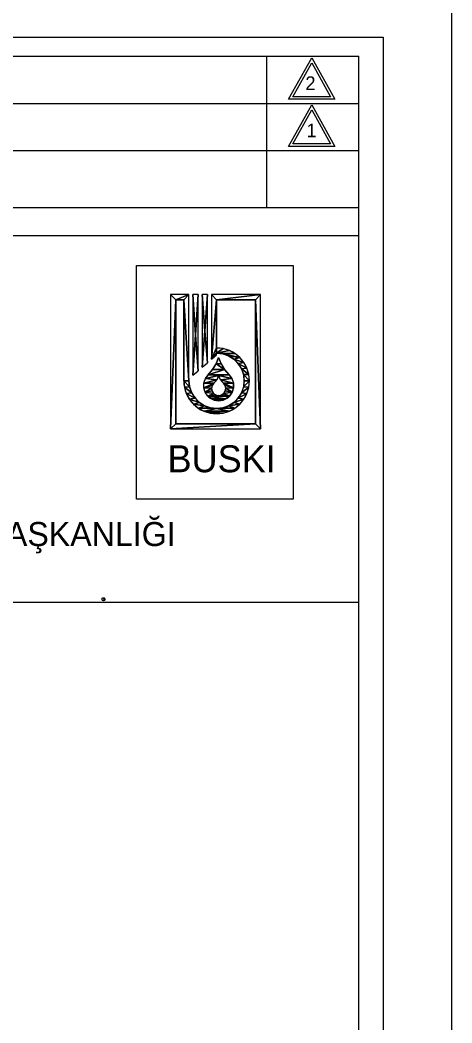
# Model space of a CAD drawing. Extents: x 314 to 1145, y -10 to 574.
# Drawn here: x 1082.1 to 1145, y 143.5 to 289.5 of the extents above; entities that cross this region are included whole.
import ezdxf

# ---------------------------------------------------------------- set-up
doc = ezdxf.new("R2010")
doc.units = 0
for name, color, linetype in [('Level 1', 7, 'Continuous'), ('Level 20', 7, 'Continuous'), ('Level 21', 7, 'Continuous'), ('Level 51', 7, 'Continuous'), ('Level 6', 7, 'Continuous'), ('Level 7', 7, 'Continuous'), ('Level 8', 7, 'Continuous')]:
    doc.layers.add(name, color=color, linetype=linetype)

msp = doc.modelspace()

# ---------------------------------------------------------------- linework, layer by layer
at = {"layer": 'Level 1'}
for p, q in [((960, 287), (1135, 287)), ((1135, 287), (1135, 0))]:
    msp.add_line(p, q, dxfattribs=at)
msp.add_lwpolyline([(1094.31, 205.37), (1094.35, 205.37), (1094.43, 205.33), (1094.48, 205.24), (1094.48, 205.07), (1094.39, 204.99), (1094.26, 204.94), (1094.14, 204.99), (1094.05, 205.07), (1094.05, 205.24), (1094.09, 205.33), (1094.18, 205.37), (1094.31, 205.37), (1094.43, 205.24), (1094.43, 205.11), (1094.35, 205.03), (1094.26, 204.94), (1094.35, 205.07), (1094.35, 205.28), (1094.31, 205.37)], dxfattribs=at)
msp.add_lwpolyline([(1094.31, 205.37), (1094.35, 205.37), (1094.43, 205.33), (1094.48, 205.24), (1094.48, 205.07), (1094.39, 204.99), (1094.26, 204.94), (1094.14, 204.99), (1094.05, 205.07), (1094.05, 205.24), (1094.09, 205.33), (1094.18, 205.37), (1094.31, 205.37), (1094.43, 205.24), (1094.43, 205.11), (1094.35, 205.03), (1094.26, 204.94), (1094.35, 205.07), (1094.35, 205.28), (1094.31, 205.37)], dxfattribs=at)
msp.add_lwpolyline([(1094.31, 205.37), (1094.35, 205.37), (1094.43, 205.33), (1094.48, 205.24), (1094.48, 205.07), (1094.39, 204.99), (1094.26, 204.94), (1094.14, 204.99), (1094.05, 205.07), (1094.05, 205.24), (1094.09, 205.33), (1094.18, 205.37), (1094.31, 205.37), (1094.43, 205.24), (1094.43, 205.11), (1094.35, 205.03), (1094.26, 204.94), (1094.35, 205.07), (1094.35, 205.28), (1094.31, 205.37)], dxfattribs=at)
msp.add_lwpolyline([(1094.31, 205.37), (1094.35, 205.37), (1094.43, 205.33), (1094.48, 205.24), (1094.48, 205.07), (1094.39, 204.99), (1094.26, 204.94), (1094.14, 204.99), (1094.05, 205.07), (1094.05, 205.24), (1094.09, 205.33), (1094.18, 205.37), (1094.31, 205.37), (1094.43, 205.24), (1094.43, 205.11), (1094.35, 205.03), (1094.26, 204.94), (1094.35, 205.07), (1094.35, 205.28), (1094.31, 205.37)], dxfattribs=at)
at = {"layer": 'Level 51'}
msp.add_lwpolyline([(314, -10), (1145, -10), (1145, 574), (314, 574)], close=True, dxfattribs=at)
at = {"layer": 'Level 6'}
for p, q in [((963.47, 284.22), (1131.45, 284.22)), ((963.47, 284.22), (1131.45, 284.22)), ((963.47, 284.22), (1131.45, 284.22)), ((963.47, 284.22), (1131.45, 284.22)), ((966.6, 284.22), (1128.32, 284.22)), ((966.6, 284.22), (1128.32, 284.22)), ((966.6, 284.22), (1128.32, 284.22)), ((966.6, 284.22), (1128.32, 284.22)), ((966.6, 284.22), (1128.32, 284.22)), ((966.6, 284.22), (1128.32, 284.22)), ((966.6, 284.22), (1128.32, 284.22)), ((966.6, 284.22), (1128.32, 284.22)), ((1118.07, 262.2), (1118.07, 284.22)), ((1118.07, 262.2), (1118.07, 284.22)), ((1118.07, 262.2), (1118.07, 284.22)), ((1118.07, 262.2), (1118.07, 284.22)), ((1131.45, 260.69), (1131.45, 284.22)), ((1131.45, 260.69), (1131.45, 284.22)), ((1131.45, 260.69), (1131.45, 284.22)), ((1131.45, 260.69), (1131.45, 284.22)), ((1131.45, 260.69), (1131.45, 284.22)), ((1131.45, 260.69), (1131.45, 284.22)), ((1131.45, 260.69), (1131.45, 284.22)), ((1131.45, 260.69), (1131.45, 284.22)), ((963.47, 277.35), (1131.45, 277.35)), ((963.47, 277.35), (1131.45, 277.35)), ((963.47, 277.35), (1131.45, 277.35)), ((963.47, 277.35), (1131.45, 277.35)), ((963.47, 270.49), (1131.45, 270.49)), ((963.47, 270.49), (1131.45, 270.49)), ((963.47, 270.49), (1131.45, 270.49)), ((963.47, 270.49), (1131.45, 270.49)), ((1131.45, 4.97), (1131.45, 267.9)), ((1131.45, 4.97), (1131.45, 267.9)), ((1131.45, 4.97), (1131.45, 267.9)), ((1131.45, 4.97), (1131.45, 267.9)), ((963.47, 262.2), (1131.45, 262.2)), ((963.47, 262.2), (1131.45, 262.2)), ((963.47, 262.2), (1131.45, 262.2)), ((963.47, 262.2), (1131.45, 262.2)), ((963.47, 258.11), (1131.45, 258.11)), ((963.47, 258.11), (1131.45, 258.11)), ((963.47, 258.11), (1131.45, 258.11)), ((963.47, 258.11), (1131.45, 258.11)), ((963.47, 204.75), (1131.45, 204.75)), ((963.47, 204.75), (1131.45, 204.75)), ((963.47, 204.75), (1131.45, 204.75)), ((963.47, 204.75), (1131.45, 204.75))]:
    msp.add_line(p, q, dxfattribs=at)
at = {"layer": 'Level 7'}
for points in [[(1121.21, 277.97), (1124.58, 284.02), (1127.95, 277.97)], [(1121.21, 277.97), (1124.58, 284.02), (1127.95, 277.97)], [(1121.21, 277.97), (1124.58, 284.02), (1127.95, 277.97)], [(1121.21, 277.97), (1124.58, 284.02), (1127.95, 277.97)], [(1121.83, 278.34), (1124.58, 283.27), (1127.33, 278.34)], [(1121.83, 278.34), (1124.58, 283.27), (1127.33, 278.34)], [(1121.83, 278.34), (1124.58, 283.27), (1127.33, 278.34)], [(1121.83, 278.34), (1124.58, 283.27), (1127.33, 278.34)], [(1121.21, 271.11), (1124.58, 277.16), (1127.95, 271.11)], [(1121.21, 271.11), (1124.58, 277.16), (1127.95, 271.11)], [(1121.21, 271.11), (1124.58, 277.16), (1127.95, 271.11)], [(1121.21, 271.11), (1124.58, 277.16), (1127.95, 271.11)], [(1121.83, 271.48), (1124.58, 276.41), (1127.33, 271.48)], [(1121.83, 271.48), (1124.58, 276.41), (1127.33, 271.48)], [(1121.83, 271.48), (1124.58, 276.41), (1127.33, 271.48)], [(1121.83, 271.48), (1124.58, 276.41), (1127.33, 271.48)]]:
    msp.add_lwpolyline(points, close=True, dxfattribs=at)
at = {"layer": 'Level 8'}
for points in [[(1099.09, 253.77), (1121.88, 253.77), (1121.88, 219.76), (1099.09, 219.76)], [(1104.03, 249.52), (1104.03, 229.97), (1104.79, 248.76)], [(1104.79, 248.76), (1106.71, 249.52), (1104.03, 249.52)], [(1104.03, 249.52), (1104.03, 229.97), (1104.79, 248.76)], [(1104.79, 248.76), (1106.71, 249.52), (1104.03, 249.52)], [(1104.79, 248.76), (1104.03, 229.97), (1104.79, 230.73)], [(1104.79, 248.76), (1104.03, 229.97), (1104.79, 230.73)], [(1106.71, 249.52), (1104.79, 248.76), (1105.95, 248.76)], [(1106.71, 249.52), (1104.79, 248.76), (1105.95, 248.76)], [(1106.71, 249.52), (1105.95, 248.76), (1106.71, 236.97)], [(1106.71, 249.52), (1105.95, 248.76), (1106.71, 236.97)], [(1105.95, 248.76), (1105.95, 236.97), (1106.71, 236.97)], [(1105.95, 248.76), (1105.95, 236.97), (1106.71, 236.97)], [(1107.67, 243.65), (1108.05, 249.52), (1107.29, 249.52)], [(1107.67, 243.65), (1107.29, 249.52), (1107.29, 237.79)], [(1107.67, 243.65), (1108.05, 249.52), (1107.29, 249.52)], [(1107.67, 243.65), (1107.29, 249.52), (1107.29, 237.79)], [(1107.67, 243.65), (1108.05, 238.43), (1108.05, 249.52)], [(1107.67, 243.65), (1108.05, 238.43), (1108.05, 249.52)], [(1109.02, 244.24), (1109.4, 249.52), (1108.64, 249.52)], [(1109.02, 244.24), (1108.64, 249.52), (1108.64, 238.96)], [(1109.02, 244.24), (1109.4, 249.52), (1108.64, 249.52)], [(1109.02, 244.24), (1108.64, 249.52), (1108.64, 238.96)], [(1109.02, 244.24), (1109.4, 239.6), (1109.4, 249.52)], [(1109.02, 244.24), (1109.4, 239.6), (1109.4, 249.52)], [(1109.98, 249.52), (1109.98, 240.12), (1110.74, 248.76)], [(1110.74, 248.76), (1117.15, 249.52), (1109.98, 249.52)], [(1109.98, 249.52), (1109.98, 240.12), (1110.74, 248.76)], [(1110.74, 248.76), (1117.15, 249.52), (1109.98, 249.52)], [(1110.74, 248.76), (1109.98, 240.12), (1110.74, 241.76)], [(1110.74, 248.76), (1109.98, 240.12), (1110.74, 241.76)], [(1117.15, 249.52), (1110.74, 248.76), (1116.4, 248.76)], [(1117.15, 249.52), (1110.74, 248.76), (1116.4, 248.76)], [(1117.15, 249.52), (1116.4, 248.76), (1117.15, 229.97)], [(1117.15, 249.52), (1116.4, 248.76), (1117.15, 229.97)], [(1116.4, 248.76), (1116.4, 230.73), (1117.15, 229.97)], [(1116.4, 248.76), (1116.4, 230.73), (1117.15, 229.97)], [(1109.02, 244.24), (1108.64, 238.96), (1109.4, 239.6)], [(1109.02, 244.24), (1108.64, 238.96), (1109.4, 239.6)], [(1107.67, 243.65), (1107.29, 237.79), (1108.05, 238.43)], [(1107.67, 243.65), (1107.29, 237.79), (1108.05, 238.43)], [(1110.74, 241.76), (1109.98, 240.12), (1110.74, 241)], [(1110.74, 241.76), (1109.98, 240.12), (1110.74, 241)], [(1110.74, 241), (1109.98, 240.12), (1110.74, 240.77)], [(1110.74, 241), (1109.98, 240.12), (1110.74, 240.77)], [(1110.74, 241.76), (1110.74, 241), (1111.67, 241.66)], [(1110.74, 241.76), (1110.74, 241), (1111.67, 241.66)], [(1111.67, 241.66), (1110.74, 241), (1112.57, 241.39)], [(1111.67, 241.66), (1110.74, 241), (1112.57, 241.39)], [(1112.57, 241.39), (1110.74, 241), (1113.39, 240.95)], [(1112.57, 241.39), (1110.74, 241), (1113.39, 240.95)], [(1110.74, 241), (1111.63, 240.9), (1113.39, 240.95)], [(1110.74, 241), (1111.63, 240.9), (1113.39, 240.95)], [(1113.39, 240.95), (1111.63, 240.9), (1114.12, 240.36)], [(1113.39, 240.95), (1111.63, 240.9), (1114.12, 240.36)], [(1111.03, 240.36), (1111.39, 239.44), (1110.67, 239.44)], [(1111.03, 240.36), (1111.39, 239.44), (1110.67, 239.44)], [(1111.63, 240.9), (1112.48, 240.6), (1114.12, 240.36)], [(1111.63, 240.9), (1112.48, 240.6), (1114.12, 240.36)], [(1112.48, 240.6), (1113.25, 240.12), (1114.12, 240.36)], [(1112.48, 240.6), (1113.25, 240.12), (1114.12, 240.36)], [(1114.12, 240.36), (1113.25, 240.12), (1114.71, 239.63)], [(1114.12, 240.36), (1113.25, 240.12), (1114.71, 239.63)], [(1113.25, 240.12), (1113.88, 239.48), (1114.71, 239.63)], [(1113.25, 240.12), (1113.88, 239.48), (1114.71, 239.63)], [(1114.71, 239.63), (1113.88, 239.48), (1115.16, 238.8)], [(1114.71, 239.63), (1113.88, 239.48), (1115.16, 238.8)], [(1113.88, 239.48), (1114.36, 238.72), (1115.16, 238.8)], [(1113.88, 239.48), (1114.36, 238.72), (1115.16, 238.8)], [(1111.9, 238.6), (1112.55, 237.85), (1109.51, 237.85)], [(1110.16, 238.6), (1111.9, 238.6), (1109.51, 237.85)], [(1111.9, 238.6), (1112.55, 237.85), (1109.51, 237.85)], [(1110.16, 238.6), (1111.9, 238.6), (1109.51, 237.85)], [(1110.67, 239.44), (1111.9, 238.6), (1110.16, 238.6)], [(1110.67, 239.44), (1111.9, 238.6), (1110.16, 238.6)], [(1111.39, 239.44), (1111.9, 238.6), (1110.67, 239.44)], [(1111.39, 239.44), (1111.9, 238.6), (1110.67, 239.44)], [(1115.16, 238.8), (1114.36, 238.72), (1115.43, 237.91)], [(1115.16, 238.8), (1114.36, 238.72), (1115.43, 237.91)], [(1114.36, 238.72), (1114.66, 237.87), (1115.43, 237.91)], [(1114.36, 238.72), (1114.66, 237.87), (1115.43, 237.91)], [(1105.95, 236.97), (1106.04, 236.04), (1106.81, 236.08)], [(1106.71, 236.97), (1105.95, 236.97), (1106.81, 236.08)], [(1105.95, 236.97), (1106.04, 236.04), (1106.81, 236.08)], [(1106.71, 236.97), (1105.95, 236.97), (1106.81, 236.08)], [(1108.87, 236.64), (1110.33, 236.62), (1108.86, 235.95)], [(1108.87, 236.64), (1110.33, 236.62), (1108.86, 235.95)], [(1110.33, 236.62), (1110.09, 236.29), (1108.86, 235.95)], [(1110.33, 236.62), (1110.09, 236.29), (1108.86, 235.95)], [(1109.1, 237.3), (1110.76, 237.13), (1108.87, 236.64)], [(1109.1, 237.3), (1110.76, 237.13), (1108.87, 236.64)], [(1110.76, 237.13), (1110.33, 236.62), (1108.87, 236.64)], [(1110.76, 237.13), (1110.33, 236.62), (1108.87, 236.64)], [(1109.51, 237.85), (1111.03, 237.73), (1109.1, 237.3)], [(1109.51, 237.85), (1111.03, 237.73), (1109.1, 237.3)], [(1111.03, 237.73), (1110.76, 237.13), (1109.1, 237.3)], [(1111.03, 237.73), (1110.76, 237.13), (1109.1, 237.3)], [(1112.55, 237.85), (1111.03, 237.73), (1109.51, 237.85)], [(1112.55, 237.85), (1111.03, 237.73), (1109.51, 237.85)], [(1112.55, 237.85), (1112.96, 237.3), (1111.03, 237.73)], [(1112.55, 237.85), (1112.96, 237.3), (1111.03, 237.73)], [(1111.03, 237.73), (1112.96, 237.3), (1111.3, 237.13)], [(1111.03, 237.73), (1112.96, 237.3), (1111.3, 237.13)], [(1112.96, 237.3), (1113.18, 236.64), (1111.3, 237.13)], [(1112.96, 237.3), (1113.18, 236.64), (1111.3, 237.13)], [(1111.3, 237.13), (1113.18, 236.64), (1111.73, 236.62)], [(1111.3, 237.13), (1113.18, 236.64), (1111.73, 236.62)], [(1113.18, 236.64), (1113.19, 235.95), (1111.73, 236.62)], [(1113.18, 236.64), (1113.19, 235.95), (1111.73, 236.62)], [(1111.73, 236.62), (1113.19, 235.95), (1111.97, 236.29)], [(1111.73, 236.62), (1113.19, 235.95), (1111.97, 236.29)], [(1115.43, 237.91), (1114.66, 237.87), (1115.52, 236.97)], [(1115.43, 237.91), (1114.66, 237.87), (1115.52, 236.97)], [(1114.66, 237.87), (1114.76, 236.97), (1115.52, 236.97)], [(1114.66, 237.87), (1114.76, 236.97), (1115.52, 236.97)], [(1115.52, 236.97), (1114.66, 236.08), (1115.43, 236.04)], [(1114.76, 236.97), (1114.66, 236.08), (1115.52, 236.97)], [(1115.52, 236.97), (1114.66, 236.08), (1115.43, 236.04)], [(1114.76, 236.97), (1114.66, 236.08), (1115.52, 236.97)], [(1106.81, 236.08), (1106.04, 236.04), (1107.11, 235.23)], [(1106.81, 236.08), (1106.04, 236.04), (1107.11, 235.23)], [(1106.04, 236.04), (1106.32, 235.14), (1107.11, 235.23)], [(1106.04, 236.04), (1106.32, 235.14), (1107.11, 235.23)], [(1107.11, 235.23), (1106.32, 235.14), (1107.59, 234.46)], [(1107.11, 235.23), (1106.32, 235.14), (1107.59, 234.46)], [(1106.32, 235.14), (1106.76, 234.32), (1107.59, 234.46)], [(1106.32, 235.14), (1106.76, 234.32), (1107.59, 234.46)], [(1110.09, 236.29), (1110, 235.89), (1108.86, 235.95)], [(1110.09, 236.29), (1110, 235.89), (1108.86, 235.95)], [(1108.86, 235.95), (1110, 235.89), (1109.07, 235.3)], [(1108.86, 235.95), (1110, 235.89), (1109.07, 235.3)], [(1110, 235.89), (1110.07, 235.49), (1109.07, 235.3)], [(1110, 235.89), (1110.07, 235.49), (1109.07, 235.3)], [(1110.07, 235.49), (1110.29, 235.14), (1109.07, 235.3)], [(1110.07, 235.49), (1110.29, 235.14), (1109.07, 235.3)], [(1109.07, 235.3), (1110.29, 235.14), (1109.47, 234.74)], [(1109.07, 235.3), (1110.29, 235.14), (1109.47, 234.74)], [(1110.29, 235.14), (1110.63, 234.91), (1109.47, 234.74)], [(1110.29, 235.14), (1110.63, 234.91), (1109.47, 234.74)], [(1111.77, 235.14), (1112.59, 234.74), (1111.43, 234.91)], [(1111.77, 235.14), (1112.59, 234.74), (1111.43, 234.91)], [(1111.99, 235.49), (1112.99, 235.3), (1111.77, 235.14)], [(1111.99, 235.49), (1112.99, 235.3), (1111.77, 235.14)], [(1112.99, 235.3), (1112.59, 234.74), (1111.77, 235.14)], [(1112.99, 235.3), (1112.59, 234.74), (1111.77, 235.14)], [(1111.97, 236.29), (1113.19, 235.95), (1112.06, 235.89)], [(1111.97, 236.29), (1113.19, 235.95), (1112.06, 235.89)], [(1112.06, 235.89), (1112.99, 235.3), (1111.99, 235.49)], [(1112.06, 235.89), (1112.99, 235.3), (1111.99, 235.49)], [(1113.19, 235.95), (1112.99, 235.3), (1112.06, 235.89)], [(1113.19, 235.95), (1112.99, 235.3), (1112.06, 235.89)], [(1114.36, 235.23), (1113.88, 234.46), (1115.16, 235.14)], [(1114.36, 235.23), (1113.88, 234.46), (1115.16, 235.14)], [(1115.16, 235.14), (1113.88, 234.46), (1114.71, 234.32)], [(1115.16, 235.14), (1113.88, 234.46), (1114.71, 234.32)], [(1114.66, 236.08), (1114.36, 235.23), (1115.43, 236.04)], [(1114.66, 236.08), (1114.36, 235.23), (1115.43, 236.04)], [(1115.43, 236.04), (1114.36, 235.23), (1115.16, 235.14)], [(1115.43, 236.04), (1114.36, 235.23), (1115.16, 235.14)], [(1107.59, 234.46), (1106.76, 234.32), (1108.23, 233.83)], [(1107.59, 234.46), (1106.76, 234.32), (1108.23, 233.83)], [(1106.76, 234.32), (1107.36, 233.59), (1108.23, 233.83)], [(1106.76, 234.32), (1107.36, 233.59), (1108.23, 233.83)], [(1108.23, 233.83), (1107.36, 233.59), (1108.99, 233.35)], [(1108.23, 233.83), (1107.36, 233.59), (1108.99, 233.35)], [(1110.63, 234.91), (1111.03, 234.83), (1109.47, 234.74)], [(1110.63, 234.91), (1111.03, 234.83), (1109.47, 234.74)], [(1111.03, 234.83), (1112.59, 234.74), (1109.47, 234.74)], [(1111.03, 234.83), (1112.59, 234.74), (1109.47, 234.74)], [(1109.47, 234.74), (1112.03, 234.33), (1110.03, 234.33)], [(1112.59, 234.74), (1112.03, 234.33), (1109.47, 234.74)], [(1109.47, 234.74), (1112.03, 234.33), (1110.03, 234.33)], [(1112.59, 234.74), (1112.03, 234.33), (1109.47, 234.74)], [(1110.03, 234.33), (1111.37, 234.11), (1110.68, 234.11)], [(1112.03, 234.33), (1111.37, 234.11), (1110.03, 234.33)], [(1110.03, 234.33), (1111.37, 234.11), (1110.68, 234.11)], [(1112.03, 234.33), (1111.37, 234.11), (1110.03, 234.33)], [(1111.43, 234.91), (1112.59, 234.74), (1111.03, 234.83)], [(1111.43, 234.91), (1112.59, 234.74), (1111.03, 234.83)], [(1113.25, 233.83), (1112.48, 233.35), (1114.12, 233.59)], [(1113.25, 233.83), (1112.48, 233.35), (1114.12, 233.59)], [(1113.88, 234.46), (1113.25, 233.83), (1114.71, 234.32)], [(1113.88, 234.46), (1113.25, 233.83), (1114.71, 234.32)], [(1114.71, 234.32), (1113.25, 233.83), (1114.12, 233.59)], [(1114.71, 234.32), (1113.25, 233.83), (1114.12, 233.59)], [(1107.36, 233.59), (1108.08, 232.99), (1108.99, 233.35)], [(1107.36, 233.59), (1108.08, 232.99), (1108.99, 233.35)], [(1108.99, 233.35), (1108.08, 232.99), (1109.84, 233.05)], [(1108.99, 233.35), (1108.08, 232.99), (1109.84, 233.05)], [(1109.84, 233.05), (1108.08, 232.99), (1110.74, 232.95)], [(1109.84, 233.05), (1108.08, 232.99), (1110.74, 232.95)], [(1108.08, 232.99), (1108.91, 232.55), (1110.74, 232.95)], [(1108.08, 232.99), (1108.91, 232.55), (1110.74, 232.95)], [(1110.74, 232.95), (1108.91, 232.55), (1112.57, 232.55)], [(1110.74, 232.95), (1108.91, 232.55), (1112.57, 232.55)], [(1108.91, 232.55), (1109.8, 232.28), (1111.67, 232.28)], [(1112.57, 232.55), (1108.91, 232.55), (1111.67, 232.28)], [(1108.91, 232.55), (1109.8, 232.28), (1111.67, 232.28)], [(1112.57, 232.55), (1108.91, 232.55), (1111.67, 232.28)], [(1111.67, 232.28), (1109.8, 232.28), (1110.74, 232.19)], [(1111.67, 232.28), (1109.8, 232.28), (1110.74, 232.19)], [(1111.63, 233.05), (1110.74, 232.95), (1113.39, 232.99)], [(1111.63, 233.05), (1110.74, 232.95), (1113.39, 232.99)], [(1113.39, 232.99), (1110.74, 232.95), (1112.57, 232.55)], [(1113.39, 232.99), (1110.74, 232.95), (1112.57, 232.55)], [(1112.48, 233.35), (1111.63, 233.05), (1113.39, 232.99)], [(1112.48, 233.35), (1111.63, 233.05), (1113.39, 232.99)], [(1114.12, 233.59), (1112.48, 233.35), (1113.39, 232.99)], [(1114.12, 233.59), (1112.48, 233.35), (1113.39, 232.99)], [(1116.4, 230.73), (1104.03, 229.97), (1117.15, 229.97)], [(1104.03, 229.97), (1116.4, 230.73), (1104.79, 230.73)], [(1116.4, 230.73), (1104.03, 229.97), (1117.15, 229.97)], [(1104.03, 229.97), (1116.4, 230.73), (1104.79, 230.73)]]:
    msp.add_lwpolyline(points, close=True, dxfattribs=at)
for points in [[(1106.71, 236.97), (1106.71, 236.97), (1106.71, 249.52), (1104.03, 249.52), (1104.03, 229.97), (1117.15, 229.97), (1117.15, 249.52), (1109.98, 249.52), (1109.98, 240.12), (1110.74, 240.77), (1110.74, 241)], [(1106.71, 236.97), (1106.71, 236.97), (1106.71, 249.52), (1104.03, 249.52), (1104.03, 229.97), (1117.15, 229.97), (1117.15, 249.52), (1109.98, 249.52), (1109.98, 240.12), (1110.74, 240.77), (1110.74, 241)], [(1105.95, 236.97), (1105.95, 236.97), (1105.95, 248.76), (1104.79, 248.76), (1104.79, 230.73), (1116.4, 230.73), (1116.4, 248.76), (1110.74, 248.76), (1110.74, 241.76)], [(1105.95, 236.97), (1105.95, 236.97), (1105.95, 248.76), (1104.79, 248.76), (1104.79, 230.73), (1116.4, 230.73), (1116.4, 248.76), (1110.74, 248.76), (1110.74, 241.76)], [(1108.05, 249.52), (1107.29, 249.52), (1107.29, 237.79), (1108.05, 238.43), (1108.05, 249.52)], [(1108.05, 249.52), (1107.29, 249.52), (1107.29, 237.79), (1108.05, 238.43), (1108.05, 249.52)], [(1108.64, 238.96), (1109.4, 239.6), (1109.4, 249.52), (1108.64, 249.52), (1108.64, 238.96)], [(1108.64, 238.96), (1109.4, 239.6), (1109.4, 249.52), (1108.64, 249.52), (1108.64, 238.96)], [(1110.74, 241.76), (1110.74, 241.76)], [(1110.74, 241.76), (1110.74, 241.76)], [(1110.74, 241), (1110.74, 241)], [(1110.74, 241), (1110.74, 241)]]:
    msp.add_lwpolyline(points, dxfattribs=at)
for centre, radius, start, end in [((1110.74, 236.97), 4.78, 180, 90), ((1110.74, 236.97), 4.78, 180, 90), ((1110.74, 236.97), 4.03, 180, 90), ((1110.74, 236.97), 4.03, 180, 90), ((1105.44, 242.02), 5.83, 314.2894, 343.392), ((1105.44, 242.02), 5.83, 314.2894, 343.392), ((1116.62, 242.02), 5.83, 196.608, 225.7106), ((1116.62, 242.02), 5.83, 196.608, 225.7106), ((1111.03, 236.27), 2.19, 133.9191, 46.0809), ((1111.03, 236.27), 2.19, 133.9191, 46.0809), ((1111.03, 235.86), 1.03, 132.7094, 47.2906), ((1111.03, 235.86), 1.03, 132.7094, 47.2906), ((1108.78, 238.37), 2.33, 311.4103, 344.0384), ((1108.78, 238.37), 2.33, 311.4103, 344.0384), ((1113.27, 238.37), 2.33, 195.9616, 228.5897), ((1113.27, 238.37), 2.33, 195.9616, 228.5897)]:
    msp.add_arc(centre, radius, start, end, dxfattribs=at)

# ---------------------------------------------------------------- texts
at = {"layer": 'Level 1'}
for s, p in [('2', (1123.65, 279.3)), ('1', (1123.82, 272.43))]:
    msp.add_text(s, height=2, dxfattribs=at).set_placement(p)
at = {"layer": 'Level 20'}
msp.add_text('PLANLAMA YATIRIM VE İNŞAAT DAİRE BAŞKANLIĞI', height=3.5, dxfattribs=at).set_placement((989.03, 212.91))
at = {"layer": 'Level 21'}
msp.add_text('BUSKI', height=3.926, dxfattribs=at).set_placement((1103.59, 223.66))
msp.add_text('BUSKI', height=3.926, dxfattribs=at).set_placement((1103.59, 223.66))

doc.saveas('drawing.dxf')
